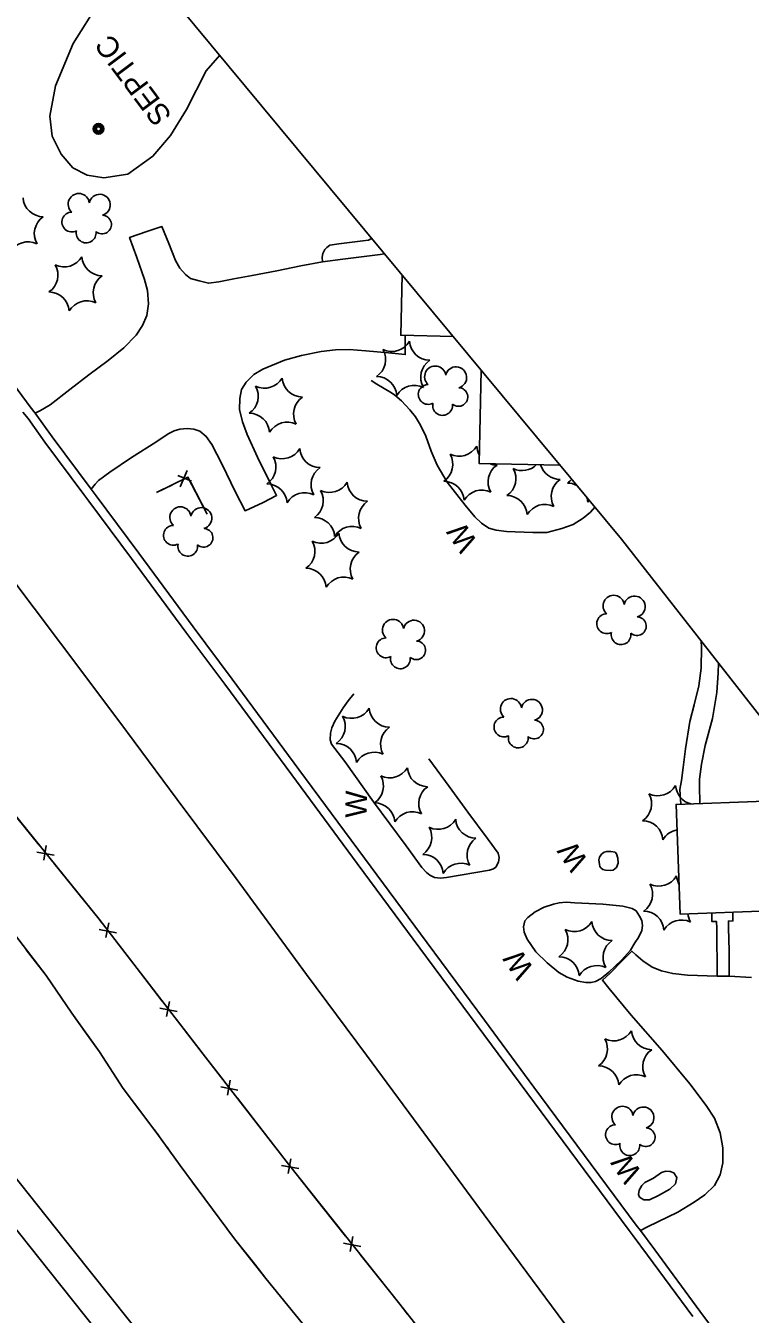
# Model space of a CAD drawing. Extents: x 353423 to 364002, y 127000 to 201942.
# Drawn here: x 357685.2 to 357888.3, y 134799.8 to 135161 of the extents above; entities that cross this region are included whole.
import ezdxf

# ---------------------------------------------------------------- set-up
doc = ezdxf.new("R2010")
doc.units = 0
for name, color, linetype in [('E_DTM_SlopeBottom', 7, 'Continuous'), ('E_DTM_SlopeTop', 7, 'Continuous'), ('E_FEN_Generic', 7, 'Continuous'), ('E_MISCPROP', 7, 'Continuous'), ('E_RDWY_Gravel', 7, 'Continuous'), ('E_STRUCT_WingWall', 7, 'Continuous'), ('E_UTL_ETransformer', 7, 'Continuous'), ('E_WTR_FlowLine', 7, 'Continuous')]:
    doc.layers.add(name, color=color, linetype=linetype)

msp = doc.modelspace()

# ---------------------------------------------------------------- linework, layer by layer
at = {"layer": 'E_DTM_SlopeBottom'}
for p, q in [((357730.43, 135036.3), (357728.53, 135031.75)), ((357731.71, 135033.32), (357727.8, 135034.93)), ((357690.95, 134931.26), (357690.25, 134927.09)), ((357688.33, 134929.35), (357693.18, 134928.5)), ((357708.46, 134909.55), (357707.66, 134905.4)), ((357705.8, 134907.7), (357710.63, 134906.74)), ((357725.48, 134887.48), (357724.67, 134883.33)), ((357722.81, 134885.64), (357727.64, 134884.67)), ((357742.5, 134865.43), (357741.71, 134861.28)), ((357739.84, 134863.59), (357744.67, 134862.63)), ((357756.9, 134841.53), (357761.74, 134840.64)), ((357759.54, 134843.42), (357758.79, 134839.25)), ((357774.23, 134819.72), (357779.08, 134818.83)), ((357776.87, 134821.61), (357776.13, 134817.44))]:
    msp.add_line(p, q, dxfattribs=at)
for points in [[(357447.21, 135217.01), (357483.92, 135174.33), (357519.83, 135132.37), (357549.54, 135096.93), (357579.24, 135062.41), (357597.79, 135040.52), (357621.03, 135013.52), (357648.32, 134981.45), (357673.52, 134950.39), (357705.77, 134910.59), (357734.92, 134872.77), (357758.85, 134841.87), (357790.03, 134802.64), (357817.81, 134767.3), (357845.11, 134732.58), (357868.77, 134701.15), (357900.84, 134659.37), (357938.33, 134610.02), (357968.56, 134569.24), (358003.7, 134521.89), (358046.03, 134465.14), (358085.2, 134412.11), (358092.67, 134402.56)], [(357844.69, 135026.09), (357843.51, 135024.69), (357841.44, 135023.01), (357838.63, 135021.18), (357835.5, 135020.07), (357831.26, 135018.94), (357827.29, 135018.92), (357819.95, 135019.28), (357817.07, 135019.6), (357815.02, 135020.19), (357812.95, 135021.53), (357811.09, 135023.31), (357808.33, 135026.64), (357803.34, 135033.05), (357800.49, 135037.8), (357798.81, 135041.72), (357797.32, 135045.98), (357795.87, 135049.03), (357794.48, 135051.34), (357792.84, 135053.36), (357790.51, 135055.9), (357788.61, 135057.48), (357787.72, 135058.12), (357783.61, 135060.5), (357781.99, 135061.58)], [(357736.06, 135024.1), (357730.67, 135034.49), (357721.85, 135030.13)], [(357726.33, 135032.35), (357721.85, 135030.13)], [(357736.06, 135024.1), (357731.48, 135032.94)], [(357814.83, 134932.89), (357817.58, 134929.1), (357817.88, 134927.81), (357817.68, 134926.58), (357816.94, 134925.19), (357816.35, 134924.71), (357815.18, 134924.33), (357803.11, 134922.21), (357801.41, 134922.05), (357799.8, 134922.21), (357798.5, 134922.91), (357797.57, 134923.64), (357796.2, 134925.08), (357791.86, 134931.14), (357782.68, 134943.44), (357774.64, 134954.72), (357770.93, 134959.61), (357770.54, 134960.82), (357770.59, 134962.67), (357770.96, 134964.19), (357771.88, 134966.03), (357774.17, 134969.77), (357775.54, 134971.8), (357777.2, 134973.74)], [(357798.2, 134955.55), (357803.91, 134947.8), (357809.13, 134940.55), (357814.83, 134932.89)], [(357682.68, 134939.08), (357688.95, 134931.35)], [(357693.09, 134926.23), (357700.22, 134917.44)], [(357700.22, 134917.44), (357705.77, 134910.59), (357706.46, 134909.68)], [(357710.48, 134904.47), (357717.4, 134895.51)], [(357717.4, 134895.51), (357723.48, 134887.62)], [(357727.49, 134882.41), (357734.41, 134873.44)], [(357734.41, 134873.44), (357734.92, 134872.77), (357740.5, 134865.57)], [(357744.53, 134860.36), (357751.46, 134851.41)], [(357751.46, 134851.41), (357757.56, 134843.54)], [(357761.63, 134838.37), (357768.68, 134829.51)], [(357768.68, 134829.51), (357774.87, 134821.71)], [(357778.97, 134816.56), (357786.01, 134807.7)], [(357786.01, 134807.7), (357790.03, 134802.64), (357792.19, 134799.89)]]:
    msp.add_lwpolyline(points, dxfattribs=at)
for points in [[(357845.99, 134925.87), (357845.86, 134927.16), (357846.05, 134927.94), (357846.61, 134928.75), (357847.33, 134929.31), (357848.03, 134929.58), (357849.15, 134929.55), (357850.38, 134929.35), (357850.78, 134928.84), (357851.16, 134927.68), (357851.21, 134926.27), (357850.81, 134925.08), (357849.88, 134924.32), (357849.17, 134924.18), (357847.73, 134924.3), (357846.91, 134924.53), (357846.43, 134924.95), (357846.15, 134925.37)], [(357855.95, 134903.93), (357854.66, 134901.85), (357852.19, 134899.11), (357848.67, 134895.73), (357846.44, 134893.97), (357844.93, 134893.11), (357843.68, 134892.85), (357842.15, 134892.81), (357840.05, 134893.15), (357836.95, 134894.31), (357834.63, 134895.65), (357831.39, 134898.33), (357828.21, 134901.43), (357825.74, 134904.93), (357824.89, 134906.97), (357824.72, 134908.46), (357825.05, 134910.07), (357825.95, 134911.08), (357828.01, 134912.63), (357830.52, 134913.97), (357833.11, 134914.77), (357834.73, 134915.14), (357836.71, 134915.34), (357839.06, 134915.15), (357846.94, 134914.82), (357852.54, 134914.18), (357855.13, 134913.57), (357856.31, 134912.88), (357857.26, 134911.41), (357857.89, 134910.19), (357858.1, 134908.83), (357857.9, 134907.43), (357856.94, 134905.47)], [(357861.1, 134838), (357863.42, 134839.59), (357864.63, 134839.97), (357865.86, 134839.86), (357866.8, 134839.46), (357867.64, 134838.16), (357867.34, 134836.39), (357865.73, 134834.9), (357862.59, 134833.13), (357859.99, 134831.92), (357858.42, 134831.92), (357857.21, 134832.69), (357856.94, 134833.44), (357857.13, 134834.64), (357857.91, 134835.94), (357858.68, 134836.74)]]:
    msp.add_lwpolyline(points, close=True, dxfattribs=at)
at = {"layer": 'E_DTM_SlopeTop'}
for points in [[(357562.31, 135167.88), (357574.21, 135150.8), (357587.08, 135132.95), (357599.49, 135116.31), (357611.28, 135099.97), (357628.47, 135076.64), (357641.47, 135059.07), (357654.36, 135041.96), (357667.76, 135023.81), (357680.18, 135007.58), (357694.95, 134987.9), (357711.59, 134965.82), (357727.66, 134944.13), (357744.14, 134922.01), (357763.88, 134895.06), (357780.75, 134872.43), (357795.51, 134852.47), (357813.69, 134827.7), (357827.25, 134809.38), (357841.61, 134789.96)], [(358028.18, 134392.9), (358000.01, 134428.74), (357971.76, 134464.97), (357946.87, 134497.14), (357917.54, 134534.71), (357893.29, 134565.79), (357863.7, 134604.36), (357833.71, 134643.36), (357808.08, 134677.2), (357781.71, 134710.97), (357753.68, 134747.73), (357728.91, 134779.61), (357698.53, 134817.83), (357671.38, 134851.83), (357641.27, 134889.51), (357615.87, 134921.19), (357589.3, 134953.78), (357562.9, 134986.28), (357534.84, 135020.47), (357508.93, 135051.35), (357481.06, 135084.46), (357451.01, 135119.99)], [(358015.83, 134396.91), (358001.99, 134414.45), (357983.82, 134437.86), (357965.64, 134461.22), (357943.39, 134489.93), (357916.54, 134524.34), (357890.09, 134558.45), (357865.41, 134590.28), (357839.77, 134623.71), (357813.43, 134657.28), (357784.59, 134694.35), (357763.33, 134721.42), (357737.87, 134753.77), (357715.04, 134782.71), (357691.82, 134812.02), (357664.99, 134845.65), (357648.47, 134866.2), (357606.79, 134918.02), (357578.03, 134953.3), (357547.68, 134989.99), (357520.1, 135023.14), (357487.3, 135062.25), (357456.58, 135098.83)], [(357884.78, 134786.39), (357874.17, 134800.67), (357861.49, 134817.86), (357857.46, 134823.3), (357856.3, 134824.81), (357845.85, 134838.92), (357827.62, 134863.44), (357813.74, 134882.27), (357797.67, 134903.92), (357780.12, 134927.68), (357761.78, 134952.53), (357743.03, 134977.89), (357732.1, 134992.55), (357716.86, 135013.19), (357704.93, 135029.24), (357703.5, 135031.14), (357692.61, 135045.75), (357687.86, 135052.36), (357686.42, 135054.22), (357675.22, 135069.3)], [(357872.16, 134799.19), (357859.48, 134816.37), (357855.46, 134821.79), (357854.3, 134823.31), (357843.85, 134837.43), (357825.61, 134861.95), (357811.73, 134880.78), (357795.66, 134902.43), (357778.11, 134926.19), (357759.76, 134951.04), (357741.02, 134976.4), (357730.09, 134991.06), (357714.85, 135011.7), (357702.93, 135027.74), (357701.5, 135029.64), (357690.59, 135044.28), (357685.86, 135050.87), (357684.43, 135052.71)]]:
    msp.add_lwpolyline(points, dxfattribs=at)
at = {"layer": 'E_FEN_Generic'}
for centre, radius, start, end in [((357690.15, 135113.18), 5.72, 184.0491, 269.814), ((357700.09, 135111.01), 2.97, 7.2614, 228.4953), ((357705.94, 135110.78), 2.97, 284.9122, 167.8855), ((357693.33, 135102.71), 5.72, 124.0491, 209.814), ((357698.13, 135106), 2.78, 90.2323, 298.0053), ((357706.6, 135105.29), 2.61, 229.6175, 87.5501), ((357685.86, 135094.72), 5.72, 64.0491, 149.814), ((357702.15, 135102.92), 2.78, 166.9093, 7.9204), ((357688.52, 135091.11), 5.72, 304.0491, 29.814), ((357695.99, 135099.11), 5.72, 244.0491, 329.814), ((357706.64, 135096.64), 5.72, 184.0491, 269.814), ((357709.83, 135086.17), 5.72, 124.0491, 209.814), ((357691.7, 135080.65), 5.72, 4.0491, 89.814), ((357702.36, 135078.17), 5.72, 64.0491, 149.814), ((357787.8, 135075.42), 5.72, 244.0491, 329.814), ((357798.46, 135072.95), 5.72, 184.0491, 269.814), ((357780.33, 135067.43), 5.72, 304.0491, 29.814), ((357801.65, 135062.48), 5.72, 124.0491, 209.814), ((357799.97, 135062.65), 2.97, 7.2614, 228.4953), ((357805.82, 135062.42), 2.97, 284.9122, 167.8855), ((357752.13, 135065.13), 5.72, 244.0491, 329.814), ((357762.79, 135062.65), 5.72, 184.0491, 269.814), ((357783.52, 135056.96), 5.72, 4.0491, 89.814), ((357798.01, 135057.65), 2.78, 90.2323, 298.0053), ((357744.66, 135057.13), 5.72, 304.0491, 29.814), ((357765.98, 135052.18), 5.72, 124.0491, 209.814), ((357794.17, 135054.49), 5.72, 64.0491, 149.814), ((357806.48, 135056.94), 2.61, 229.6175, 87.5501), ((357802.03, 135054.57), 2.78, 166.9093, 7.9204), ((357747.85, 135046.66), 5.72, 4.0491, 89.814), ((357758.51, 135044.19), 5.72, 64.0491, 149.814), ((357757.07, 135045.34), 5.72, 244.0491, 329.814), ((357767.72, 135042.86), 5.72, 184.0491, 269.814), ((357806.65, 135046.05), 5.72, 244.0491, 329.814), ((357817.31, 135043.58), 5.72, 184.0491, 209.4931), ((357749.59, 135037.34), 5.72, 304.0491, 29.814), ((357799.18, 135038.06), 5.72, 304.0491, 29.814), ((357770.91, 135032.39), 5.72, 124.0491, 209.814), ((357820.49, 135033.11), 5.72, 124.0491, 209.814), ((357817.31, 135043.58), 5.72, 247.9167, 269.814), ((357816.87, 135034.04), 5.72, 304.0491, 29.814), ((357824.34, 135042.04), 5.72, 244.0491, 314.8365), ((357835, 135039.56), 5.72, 196.3602, 269.814), ((357752.78, 135026.87), 5.72, 4.0491, 89.814), ((357770.36, 135035.9), 5.72, 244.0491, 329.814), ((357781.02, 135033.43), 5.72, 184.0491, 269.814), ((357802.36, 135027.59), 5.72, 4.0491, 89.814), ((357838.19, 135029.1), 5.72, 124.0491, 209.814), ((357833.82, 135037.56), 5.72, 304.0491, 320.1933), ((357837, 135027.1), 5.72, 62.5094, 89.814), ((357763.44, 135024.4), 5.72, 64.0491, 149.814), ((357762.89, 135027.9), 5.72, 304.0491, 29.814), ((357813.02, 135025.12), 5.72, 64.0491, 149.814), ((357820.06, 135023.58), 5.72, 4.0491, 89.814), ((357837, 135027.1), 5.72, 4.0491, 16.8813), ((357847.66, 135024.62), 5.72, 143.2717, 149.814), ((357728.55, 135023.19), 2.97, 7.2614, 228.4953), ((357734.4, 135022.96), 2.97, 284.9122, 167.8855), ((357784.21, 135022.96), 5.72, 124.0491, 209.814), ((357830.72, 135021.1), 5.72, 64.0491, 149.814), ((357726.59, 135018.18), 2.78, 90.2323, 298.0053), ((357766.08, 135017.44), 5.72, 4.0491, 89.814), ((357776.74, 135014.96), 5.72, 64.0491, 149.814), ((357735.06, 135017.48), 2.61, 229.6175, 87.5501), ((357768.01, 135021.67), 5.72, 244.0491, 329.814), ((357778.66, 135019.2), 5.72, 184.0491, 269.814), ((357730.61, 135015.1), 2.78, 166.9093, 7.9204), ((357760.54, 135013.68), 5.72, 304.0491, 29.814), ((357781.85, 135008.73), 5.72, 124.0491, 209.814), ((357763.72, 135003.21), 5.72, 4.0491, 89.814), ((357774.38, 135000.74), 5.72, 64.0491, 149.814), ((357849.99, 134998.39), 2.97, 7.2614, 228.4953), ((357855.84, 134998.16), 2.97, 284.9122, 167.8855), ((357848.03, 134993.39), 2.78, 90.2323, 298.0053), ((357788.15, 134991.63), 2.97, 7.2614, 228.4953), ((357794, 134991.4), 2.97, 284.9122, 167.8855), ((357856.5, 134992.68), 2.61, 229.6175, 87.5501), ((357786.19, 134986.63), 2.78, 90.2323, 298.0053), ((357794.65, 134985.92), 2.61, 229.6175, 87.5501), ((357852.05, 134990.31), 2.78, 166.9093, 7.9204), ((357790.2, 134983.55), 2.78, 166.9093, 7.9204), ((357821.19, 134969.45), 2.97, 7.2614, 228.4953), ((357827.04, 134969.22), 2.97, 284.9122, 167.8855), ((357769.03, 134964.59), 5.72, 304.0491, 29.814), ((357776.5, 134972.58), 5.72, 244.0491, 329.814), ((357787.16, 134970.11), 5.72, 184.0491, 269.814), ((357819.23, 134964.45), 2.78, 90.2323, 298.0053), ((357790.35, 134959.64), 5.72, 124.0491, 209.814), ((357827.69, 134963.74), 2.61, 229.6175, 87.5501), ((357772.22, 134954.12), 5.72, 4.0491, 89.814), ((357823.24, 134961.37), 2.78, 166.9093, 7.9204), ((357782.88, 134951.65), 5.72, 64.0491, 149.814), ((357787.22, 134955.91), 5.72, 244.0491, 329.814), ((357797.87, 134953.43), 5.72, 184.0491, 269.814), ((357779.75, 134947.91), 5.72, 304.0491, 29.814), ((357801.06, 134942.96), 5.72, 124.0491, 209.814), ((357854.9, 134942.9), 5.72, 304.0491, 29.814), ((357862.37, 134950.89), 5.72, 244.0491, 329.814), ((357873.03, 134948.42), 5.72, 184.0491, 255.7046), ((357782.93, 134937.44), 5.72, 4.0491, 89.814), ((357793.59, 134934.97), 5.72, 64.0491, 149.814), ((357800.76, 134941.46), 5.72, 244.0491, 329.814), ((357811.41, 134938.99), 5.72, 184.0491, 269.814), ((357858.09, 134932.43), 5.72, 4.0491, 89.814), ((357793.29, 134933.47), 5.72, 304.0491, 29.814), ((357868.75, 134929.96), 5.72, 100.11, 149.814), ((357814.6, 134928.52), 5.72, 124.0491, 209.814), ((357796.47, 134923), 5.72, 4.0491, 89.814), ((357807.13, 134920.53), 5.72, 64.0491, 149.814), ((357855.19, 134917.57), 5.72, 304.0491, 29.814), ((357862.66, 134925.57), 5.72, 244.0491, 329.814), ((357873.32, 134923.1), 5.72, 184.0491, 208.4742), ((357858.37, 134907.11), 5.72, 4.0491, 89.814), ((357838.91, 134912.79), 5.72, 244.0491, 329.814), ((357849.57, 134910.31), 5.72, 184.0491, 269.814), ((357869.03, 134904.63), 5.72, 64.0491, 149.814), ((357876.5, 134912.63), 5.72, 185.3858, 209.814), ((357831.44, 134904.79), 5.72, 304.0491, 29.814), ((357852.75, 134899.85), 5.72, 124.0491, 209.814), ((357834.62, 134894.33), 5.72, 4.0491, 89.814), ((357845.28, 134891.85), 5.72, 64.0491, 149.814), ((357842.53, 134874.18), 5.72, 304.0491, 29.814), ((357850, 134882.18), 5.72, 244.0491, 329.814), ((357860.66, 134879.71), 5.72, 184.0491, 269.814), ((357863.84, 134869.24), 5.72, 124.0491, 209.814), ((357845.71, 134863.72), 5.72, 4.0491, 89.814), ((357856.37, 134861.24), 5.72, 64.0491, 149.814), ((357852.46, 134855.17), 2.97, 7.2614, 228.4953), ((357858.31, 134854.94), 2.97, 284.9122, 167.8855), ((357850.5, 134850.17), 2.78, 90.2323, 298.0053), ((357858.97, 134849.46), 2.61, 229.6175, 87.5501), ((357854.52, 134847.08), 2.78, 166.9093, 7.9204)]:
    msp.add_arc(centre, radius, start, end, dxfattribs=at)
at = {"layer": 'E_MISCPROP'}
for points in [[(357687.86, 135052.36), (357689.33, 135053.15), (357692.1, 135054.73), (357697.54, 135059.01), (357702.89, 135063.12), (357708.33, 135067.19), (357712.68, 135070.75), (357716.16, 135074.26), (357717.92, 135077.02), (357719.11, 135079.79), (357719.57, 135083.05), (357719.34, 135086.77), (357718.51, 135089.89), (357716.32, 135096.06), (357714.32, 135101.69), (357719.19, 135103.33), (357723.36, 135104.71), (357725.34, 135099.99), (357727.16, 135095.24), (357728.42, 135093.06), (357729.98, 135091.24), (357731.36, 135090.17), (357733.78, 135089.49), (357736.41, 135088.84), (357739.31, 135089.22), (357743.54, 135090.1), (357748.65, 135090.99), (357755.54, 135092.26), (357762.35, 135093.73), (357768.37, 135094.81), (357774.05, 135095.61), (357780.8, 135096.43), (357784.53, 135096.87), (357785.8, 135097.04)], [(357782.18, 135101.4), (357782.13, 135101.36), (357781.29, 135100.88), (357779.72, 135100.68), (357772.97, 135099.9), (357770.43, 135099.48), (357769.59, 135098.88), (357769, 135098.27), (357768.43, 135097.17), (357768.32, 135096.14), (357768.37, 135094.81)], [(357791.59, 135074.23), (357791.59, 135073.23), (357791.56, 135068.85), (357786.86, 135069.35), (357780.56, 135069.88), (357775.86, 135070.21), (357771.98, 135070.15), (357768.04, 135069.68), (357762.52, 135068.54), (357757.69, 135067.3), (357751.68, 135064.78), (357749.16, 135063.27), (357746.96, 135061.06), (357745.7, 135059.07), (357745.18, 135056.48), (357745.14, 135053.47), (357745.92, 135049.94), (357747.23, 135046.39), (357750.2, 135040.08), (357754.01, 135032.33), (357755.5, 135029.36), (357751.73, 135027.32), (357746.67, 135025.05), (357744, 135030.24), (357740.16, 135038.19), (357737.41, 135043.64), (357735.78, 135045.91), (357734, 135047.4), (357732.28, 135047.94), (357730.46, 135048.07), (357728.39, 135047.92), (357726.81, 135047.42), (357725.14, 135046.64), (357721.69, 135044.3), (357714.89, 135039.97), (357708.75, 135035.88), (357705.63, 135033.57), (357704.65, 135032.52), (357703.5, 135031.14)], [(357868.77, 134942.77), (357868.56, 134946.88), (357869, 134949.47), (357869.47, 134953.05), (357870.14, 134958.28), (357871.34, 134965.97), (357872.58, 134970.69), (357873.83, 134975.98), (357874.46, 134980.92), (357874.57, 134986.83), (357874.54, 134988.5)], [(357879.4, 134982.28), (357879.29, 134979.59), (357878.86, 134974.15), (357877.67, 134966.83), (357875.66, 134959.24), (357874.57, 134954.02), (357874.01, 134949.83), (357874.05, 134948.06), (357874.09, 134942.96)], [(357877.52, 134912.33), (357877.54, 134909.88), (357878.82, 134909.89), (357878.86, 134908.03), (357879, 134894.6)], [(357882.35, 134894.56), (357882.33, 134901.7), (357882.16, 134908.11), (357882.13, 134910.05), (357883.41, 134910.1), (357883.42, 134912.54)], [(357888.65, 134894.18), (357882.35, 134894.56), (357879, 134894.6), (357870.66, 134894.86), (357866.54, 134895.3), (357863.39, 134896.13), (357860.77, 134897.15), (357858.13, 134898.87), (357856.23, 134900.57), (357855.1, 134901.59), (357852.35, 134898.86), (357848.99, 134895.39), (357846.84, 134893.43), (357848.64, 134891.27), (357854.92, 134883.63), (357863.62, 134873.74), (357871.35, 134864.41), (357875.94, 134858.38), (357878.28, 134854.77), (357879.87, 134850.72), (357880.62, 134846.48), (357880.55, 134842.23), (357879.85, 134838.9), (357878.24, 134835.89), (357875.53, 134833.32), (357872.58, 134831.29), (357867.92, 134828.44), (357862.36, 134825.74), (357859.51, 134824.32), (357857.46, 134823.3)]]:
    msp.add_lwpolyline(points, dxfattribs=at)
at = {"layer": 'E_RDWY_Gravel'}
msp.add_lwpolyline([(358332.15, 134382.33), (358183.85, 134581.8), (358077.08, 134725.09), (357967.65, 134869.51), (357852.14, 135017.13), (357694.09, 135207.52), (357601.28, 135315.73)], dxfattribs=at)
at = {"layer": 'E_STRUCT_WingWall'}
for points in [[(357681.11, 134907.54), (357690.9, 134894.81), (357698.1, 134884.21), (357705.86, 134873.35), (357712.53, 134863.14), (357721.95, 134850.62), (357728.49, 134841.49), (357735.43, 134832.14), (357743.68, 134820.93), (357752.52, 134809.88), (357762.8, 134797.22)], [(357685.37, 134902.01), (357690.9, 134894.81), (357698.1, 134884.21), (357702.23, 134878.43)], [(357702.23, 134878.43), (357705.86, 134873.35), (357712.53, 134863.14), (357718.89, 134854.7)], [(357721.29, 134851.5), (357721.95, 134850.62), (357722.48, 134849.89)], [(357724.8, 134846.64), (357725.97, 134845.01)], [(357728.29, 134841.76), (357728.49, 134841.49), (357729.48, 134840.15)], [(357731.86, 134836.94), (357735.43, 134832.14), (357743.68, 134820.93), (357749.37, 134813.82)], [(357749.37, 134813.82), (357752.52, 134809.88), (357762.8, 134797.22), (357767.85, 134791.48)]]:
    msp.add_lwpolyline(points, dxfattribs=at)
at = {"layer": 'E_UTL_ETransformer'}
for centre, radius in [((357705.59, 135132.11), 1.5), ((357705.6, 135132.11), 1.22), ((357705.61, 135132.1), 0.968), ((357705.62, 135132.07), 0.605)]:
    msp.add_circle(centre, radius, dxfattribs=at)
at = {"layer": 'E_WTR_FlowLine'}
for points in [[(357739.58, 135152.73), (357735.78, 135148.41), (357730.28, 135137.53), (357725.79, 135130.28), (357720.84, 135124.4), (357713.84, 135119.43), (357707.09, 135118.39), (357702.39, 135119.09), (357698.43, 135121.13), (357695.17, 135125.01), (357692.59, 135130.08), (357691.94, 135135.61), (357693.53, 135144.15), (357698.49, 135156.04), (357705.73, 135167.44), (357714.49, 135179.31), (357716.12, 135180.99)], [(357804.98, 135073.93), (357790.29, 135074.26), (357790.67, 135091.17)], [(357834.95, 135037.83), (357812.27, 135038.34), (357812.86, 135064.44)]]:
    msp.add_lwpolyline(points, dxfattribs=at)
msp.add_lwpolyline([(357892.47, 134943.61), (357893.56, 134912.9), (357868.58, 134912.01), (357867.49, 134942.73)], close=True, dxfattribs=at)

# ---------------------------------------------------------------- texts
at = {"layer": 'E_DTM_SlopeBottom'}
for rotation, p in [(123.8377, (357812.11, 135016.07)), (88.8377, (357780.74, 134938.92)), (123.8377, (357843.11, 134926.67)), (123.8377, (357827.94, 134896.39)), (123.8377, (357858.15, 134839.27))]:
    msp.add_text('W', height=6, rotation=rotation, dxfattribs=at).set_placement(p)
at = {"layer": 'E_UTL_ETransformer'}
msp.add_text('SEPTIC', height=6, rotation=126.8378, dxfattribs=at).set_placement((357726.4, 135135.85))

doc.saveas('drawing.dxf')
